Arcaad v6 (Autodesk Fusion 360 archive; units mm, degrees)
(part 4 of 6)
sketch "Sketch3" plane through (-5.5, 0, 0) normal (-1, 0, 0) x axis (0, -1, 0)
  line L1 (13, -14.5) -> (557.5, -14.5)
  circle C1 centre (557.5, -14.5) radius 7
  arc A1 centre (557.5, -14.5) radius 6.4 clockwise from (562.2211, -10.1789) to (562.7633, -10.8588)
  arc A2 centre (563.2662, -11.7231) radius 1 clockwise from (563.6284, -12.6553) to (562.7633, -10.8588)
  arc A3 centre (557.5, -14.5) radius 6.4 clockwise from (563.6284, -12.6553) to (563.8219, -13.5031)
  arc A4 centre (563.9, -14.5) radius 1 clockwise from (563.8219, -15.4969) to (563.8219, -13.5031)
  arc A5 centre (557.5, -14.5) radius 6.4 clockwise from (563.8219, -15.4969) to (563.6284, -16.3447)
  arc A6 centre (563.2662, -17.2769) radius 1 clockwise from (562.7633, -18.1412) to (563.6284, -16.3447)
  arc A7 centre (557.5, -14.5) radius 6.4 clockwise from (562.7633, -18.1412) to (562.2211, -18.8211)
  arc A8 centre (561.4903, -19.5037) radius 1 clockwise from (560.6622, -20.0642) to (562.2211, -18.8211)
  arc A9 centre (557.5, -14.5) radius 6.4 clockwise from (560.6622, -20.0642) to (559.8787, -20.4415)
  arc A10 centre (558.9241, -20.7395) radius 1 clockwise from (557.9348, -20.8852) to (559.8787, -20.4415)
  arc A11 centre (557.5, -14.5) radius 6.4 clockwise from (557.9348, -20.8852) to (557.0652, -20.8852)
  arc A12 centre (556.0759, -20.7395) radius 1 clockwise from (555.1213, -20.4415) to (557.0652, -20.8852)
  arc A13 centre (557.5, -14.5) radius 6.4 clockwise from (555.1213, -20.4415) to (554.3378, -20.0642)
  arc A14 centre (553.5097, -19.5037) radius 1 clockwise from (552.7789, -18.8211) to (554.3378, -20.0642)
  arc A15 centre (557.5, -14.5) radius 6.4 clockwise from (552.7789, -18.8211) to (552.2367, -18.1412)
  arc A16 centre (551.7338, -17.2769) radius 1 clockwise from (551.3716, -16.3447) to (552.2367, -18.1412)
  arc A17 centre (557.5, -14.5) radius 6.4 clockwise from (551.3716, -16.3447) to (551.1781, -15.4969)
  arc A18 centre (551.1, -14.5) radius 1 clockwise from (551.1781, -13.5031) to (551.1781, -15.4969)
  arc A19 centre (557.5, -14.5) radius 6.4 clockwise from (551.1781, -13.5031) to (551.3716, -12.6553)
  arc A20 centre (551.7338, -11.7231) radius 1 clockwise from (552.2367, -10.8588) to (551.3716, -12.6553)
  arc A21 centre (557.5, -14.5) radius 6.4 clockwise from (552.2367, -10.8588) to (552.7789, -10.1789)
  arc A22 centre (553.5097, -9.4963) radius 1 clockwise from (554.3378, -8.9358) to (552.7789, -10.1789)
  arc A23 centre (557.5, -14.5) radius 6.4 clockwise from (554.3378, -8.9358) to (555.1213, -8.5585)
  arc A24 centre (556.0759, -8.2605) radius 1 clockwise from (557.0652, -8.1148) to (555.1213, -8.5585)
  arc A25 centre (557.5, -14.5) radius 6.4 clockwise from (557.0652, -8.1148) to (557.9348, -8.1148)
  arc A26 centre (558.9241, -8.2605) radius 1 clockwise from (559.8787, -8.5585) to (557.9348, -8.1148)
  arc A27 centre (557.5, -14.5) radius 6.4 clockwise from (559.8787, -8.5585) to (560.6622, -8.9358)
  arc A28 centre (561.4903, -9.4963) radius 1 clockwise from (562.2211, -10.1789) to (560.6622, -8.9358)
  arc A29 centre (12.5, -14.5) radius 6.4 clockwise from (12.9348, -20.8852) to (12.9348, -8.1148)
  point P2 (557.5, -14.5)
  point P46 (557.5, -14.5)
  point P45 (13, -14.5)
  point P47 (13, -14.5)
  point P49 (12.9348, -8.1148)
  point P53 (12.9348, -8.1148)
  point P50 (12.9348, -20.8852)
  point P52 (12.9348, -20.8852)
  point P48 (12.5, -14.5)
  point P51 (12.5, -14.5)
  coincident P2 P46
  coincident P45 P47
  coincident P49 P53
  coincident P50 P52
  coincident P48 P51
sketch "Sketch4" plane through (0, 0, 0) normal (1, 0, 0) x axis (0, 0, -1)
sketch "Sketch5" plane through (-5.5, 0, 0) normal (-1, 0, 0) x axis (0, -1, 0)
sketch "Sketch6" plane through (-6, 0, 0) normal (-1, 0, 0) x axis (0, 0, 1)
  line L1 (-14.5, -13) -> (-14.5, -557.5)
  line L2 (-50, -285.25) -> (-14.5, -285.25)
  line L3 (20, -285.25) -> (-14.5, -285.25)
  line L4 (-20.8852, -285.25) -> (-20.8852, -12.9348)
  line L5 (-8.1148, -285.25) -> (-8.1148, -12.0652)
  line L6 (-20.8852, -285.25) -> (-20.8852, -557.5652)
  line L7 (-8.1148, -285.25) -> (-8.1148, -558.4348)
  circle C1 centre (-14.5, -12.5) radius 7
  arc A1 centre (-14.5, -12.5) radius 6.4 clockwise from (-10.1789, -17.2211) to (-10.8588, -17.7633)
  arc A2 centre (-11.7231, -18.2662) radius 1 clockwise from (-12.6553, -18.6284) to (-10.8588, -17.7633)
  arc A3 centre (-14.5, -12.5) radius 6.4 clockwise from (-12.6553, -18.6284) to (-13.5031, -18.8219)
  arc A4 centre (-14.5, -18.9) radius 1 clockwise from (-15.4969, -18.8219) to (-13.5031, -18.8219)
  arc A5 centre (-14.5, -12.5) radius 6.4 clockwise from (-15.4969, -18.8219) to (-16.3447, -18.6284)
  arc A6 centre (-17.2769, -18.2662) radius 1 clockwise from (-18.1412, -17.7633) to (-16.3447, -18.6284)
  arc A7 centre (-14.5, -12.5) radius 6.4 clockwise from (-18.1412, -17.7633) to (-18.8211, -17.2211)
  arc A8 centre (-19.5037, -16.4903) radius 1 clockwise from (-20.0642, -15.6622) to (-18.8211, -17.2211)
  arc A9 centre (-14.5, -12.5) radius 6.4 clockwise from (-20.0642, -15.6622) to (-20.4415, -14.8787)
  arc A10 centre (-20.7395, -13.9241) radius 1 clockwise from (-20.8852, -12.9348) to (-20.4415, -14.8787)
  arc A11 centre (-14.5, -12.5) radius 6.4 clockwise from (-20.8852, -12.9348) to (-20.8852, -12.0652)
  arc A12 centre (-20.7395, -11.0759) radius 1 clockwise from (-20.4415, -10.1213) to (-20.8852, -12.0652)
  arc A13 centre (-14.5, -12.5) radius 6.4 clockwise from (-20.4415, -10.1213) to (-20.0642, -9.3378)
  arc A14 centre (-19.5037, -8.5097) radius 1 clockwise from (-18.8211, -7.7789) to (-20.0642, -9.3378)
  arc A15 centre (-14.5, -12.5) radius 6.4 clockwise from (-18.8211, -7.7789) to (-18.1412, -7.2367)
  arc A16 centre (-17.2769, -6.7338) radius 1 clockwise from (-16.3447, -6.3716) to (-18.1412, -7.2367)
  arc A17 centre (-14.5, -12.5) radius 6.4 clockwise from (-16.3447, -6.3716) to (-15.4969, -6.1781)
  arc A18 centre (-14.5, -6.1) radius 1 clockwise from (-13.5031, -6.1781) to (-15.4969, -6.1781)
  arc A19 centre (-14.5, -12.5) radius 6.4 clockwise from (-13.5031, -6.1781) to (-12.6553, -6.3716)
  arc A20 centre (-11.7231, -6.7338) radius 1 clockwise from (-10.8588, -7.2367) to (-12.6553, -6.3716)
  arc A21 centre (-14.5, -12.5) radius 6.4 clockwise from (-10.8588, -7.2367) to (-10.1789, -7.7789)
  arc A22 centre (-9.4963, -8.5097) radius 1 clockwise from (-8.9358, -9.3378) to (-10.1789, -7.7789)
  arc A23 centre (-14.5, -12.5) radius 6.4 clockwise from (-8.9358, -9.3378) to (-8.5585, -10.1213)
  arc A24 centre (-8.2605, -11.0759) radius 1 clockwise from (-8.1148, -12.0652) to (-8.5585, -10.1213)
  arc A25 centre (-14.5, -12.5) radius 6.4 clockwise from (-8.1148, -12.0652) to (-8.1148, -12.9348)
  arc A26 centre (-8.2605, -13.9241) radius 1 clockwise from (-8.5585, -14.8787) to (-8.1148, -12.9348)
  arc A27 centre (-14.5, -12.5) radius 6.4 clockwise from (-8.5585, -14.8787) to (-8.9358, -15.6622)
  arc A28 centre (-9.4963, -16.4903) radius 1 clockwise from (-10.1789, -17.2211) to (-8.9358, -15.6622)
  arc A29 centre (-14.5, -12.5) radius 6.4 clockwise from (-20.8852, -12.9348) to (-8.1148, -12.9348)
  arc A30 centre (-14.5, -558) radius 6.4 clockwise from (-8.1148, -557.5652) to (-20.8852, -557.5652)
  point P40 (-8.1148, -12.9348)
  point P46 (-8.1148, -12.9348)
  point P17 (-20.8852, -12.9348)
  point P47 (-20.8852, -12.9348)
  point P50 (-14.5, -285.25)
  point P53 (-20.8852, -12.9348)
  point P54 (-20.8852, -285.25)
  point P38 (-8.1148, -12.0652)
  point P55 (-8.1148, -12.0652)
  point P56 (-8.1148, -285.25)
  point P58 (-8.1148, -557.5652)
  point P59 (-20.8852, -557.5652)
  point P60 (-20.8852, -557.5652)
  point P61 (-20.8852, -285.25)
  point P62 (-8.1148, -558.4348)
  point P63 (-8.1148, -285.25)
  coincident P40 P46
  coincident P17 P47
  midpoint L1 P50
  perpendicular L1 L2
  perpendicular L1 L3
  coincident P17 P53
  coincident L2 P54
  perpendicular L2 L4
  coincident P38 P55
  coincident L3 P56
  perpendicular L3 L5
  symmetric P46 L3 P58
  symmetric P47 L3 P59
  symmetric A29 L3 A30
  symmetric L3 P53 P60
  symmetric L3 P54 P61
  symmetric L3 P55 P62
  symmetric L3 P56 P63
work_plane "WorkPlane2" AlongDistance 0
work_plane "WorkPlane1" AlongDistance 0
sketch "Sketch7" plane through (-13, -13.8394, -20.222) normal (1, 0, 0) x axis (0, 0, -1)
  line L1 (0.6632, -271.4106) -> (0.6632, 0.9046)
  line L2 (-12.1072, -271.4106) -> (-12.1072, 1.7742)
  line L3 (0.6632, -271.4106) -> (0.6632, -543.7258)
  line L4 (-12.1072, -271.4106) -> (-12.1072, -544.5954)
  line L5 (-13.1072, -271.4106) -> (-13.1072, 1.7742)
  line L6 (1.6632, -271.4106) -> (1.6632, 0.9046)
  line L7 (-13.1072, -271.4106) -> (-13.1072, -544.5954)
  line L8 (1.6632, -271.4106) -> (1.6632, -543.7258)
  arc A1 centre (-5.722, 1.3394) radius 6.4 clockwise from (-12.1072, 0.9046) to (0.6632, 0.9046)
  arc A2 centre (-5.722, -544.1606) radius 6.4 clockwise from (0.6632, -543.7258) to (-12.1072, -543.7258)
  arc A3 centre (-5.722, 1.3394) radius 7.4 clockwise from (-13.1049, 0.8367) to (1.6609, 0.8367)
  arc A4 centre (-5.722, -544.1606) radius 7.4 clockwise from (1.6609, -543.6579) to (-13.1049, -543.6579)
  dimension "d24" = 1
  dimension "d25" = -1
  dimension "d26" = 1
  dimension "d27" = -1
  dimension "d28" = 1
  dimension "d29" = 1
extrude "Extrude5" new body sketch "Sketch7" along normal blind 7
copy_paste_bodies "CopyPasteBodies1"
move "Move1" TranslateX 0 TranslateY 0 TranslateZ -245
sketch "Sketch8" plane through (0, 0, 0) normal (-1, 0, 0) x axis (0, 0, 1)
  line L1 (13, -585) -> (-287, -585)
  line L2 (13, 15) -> (13, -585)
  line L3 (-287, 15) -> (13, 15)
  line L4 (-287, -585) -> (-287, 15)
  line L5 (-31.0605, -31.0605) -> (-243.9395, -31.0605)
  line L6 (-31.0605, -553.3145) -> (-31.0605, -31.0605)
  line L7 (-243.9395, -553.3145) -> (-31.0605, -553.3145)
  line L8 (-243.9395, -31.0605) -> (-243.9395, -553.3145)
  line L9 (318.9395, -553.3145) -> (318.9395, -31.0605)
  line L10 (106.0605, -553.3145) -> (318.9395, -553.3145)
  line L11 (318.9395, -31.0605) -> (106.0605, -31.0605)
  line L12 (106.0605, -31.0605) -> (106.0605, -553.3145)
  line L13 (106.0605, -513.3145) -> (318.9395, -513.3145)
  line L14 (-243.9395, -513.3145) -> (-31.0605, -513.3145)
  circle C1 centre (-259.5, -557.5) radius 2.5
  circle C2 centre (-14.5, -557.5) radius 2.5
  circle C3 centre (-259.5, -12.5) radius 2.5
  circle C4 centre (-14.5, -12.5) radius 2.5
  circle C5 centre (335.5, -557.5) radius 2.5
  circle C6 centre (90.5, -557.5) radius 2.5
  circle C7 centre (282.8591, -471.833) radius 20
  circle C8 centre (164.4009, -468.2067) radius 20
  circle C9 centre (225, -350) radius 20
  circle C10 centre (142.0186, -331.3336) radius 20
  circle C11 centre (226.3259, -235.6181) radius 20
  circle C12 centre (287.5847, -183.7959) radius 20
  circle C13 centre (162.57, -169.7572) radius 20
  circle C14 centre (129.8493, -225.5922) radius 20
  circle C15 centre (131.0664, -99.9179) radius 20
  circle C16 centre (214.8765, -425.1239) radius 15
  circle C17 centre (299.5333, -431.8087) radius 15
  circle C18 centre (260, -400) radius 15
  circle C19 centre (171.7339, -386.7903) radius 15
  circle C20 centre (195.3109, -315.7507) radius 15
  circle C21 centre (281.4332, -277.091) radius 15
  circle C22 centre (209.1847, -144.1327) radius 15
  circle C23 centre (211.4323, -94.5944) radius 15
  circle C24 centre (290.7241, -95.0468) radius 15
  circle C25 centre (210, -490) radius 10
  circle C26 centre (125.7856, -445.9118) radius 10
  circle C27 centre (130, -370) radius 10
  circle C28 centre (126.5404, -269.0631) radius 10
  circle C29 centre (176.569, -222.7107) radius 10
  circle C30 centre (233.5979, -275.0095) radius 10
  circle C31 centre (301.465, -233.4303) radius 10
  circle C32 centre (304.9225, -139.6703) radius 10
  circle C33 centre (260, -150) radius 10
  circle C34 centre (262.5929, -72.5429) radius 10
  circle C35 centre (122.2213, -136.25) radius 10
  circle C36 centre (219.3465, -184.5454) radius 10
  circle C37 centre (260, -440) radius 10
  circle C38 centre (304.2815, -314.2782) radius 10
  circle C39 centre (270, -320) radius 10
  circle C40 centre (177.2901, -424.5516) radius 10
  circle C41 centre (122.2213, -494.7374) radius 10
  circle C42 centre (298.2256, -504.4554) radius 10
  circle C43 centre (167.9513, -503.3757) radius 7
  circle C44 centre (244.5735, -496.3966) radius 7
  circle C45 centre (230, -460) radius 7
  circle C46 centre (183.3051, -345.8239) radius 7
  circle C47 centre (210, -390) radius 7
  circle C48 centre (150, -300) radius 7
  circle C49 centre (250, -120) radius 7
  circle C50 centre (168.2131, -77.1992) radius 7
  circle C51 centre (167.9513, -124.3724) radius 7
  circle C52 centre (140, -410) radius 7
  circle C53 centre (120, -180) radius 7
  circle C54 centre (193.9116, -281.9568) radius 7
  circle C55 centre (272.9439, -242.5691) radius 7
  circle C56 centre (183.3051, -345.8239) radius 7
  circle C57 centre (183.3051, -345.8239) radius 7
  circle C58 centre (212.9765, -58.095) radius 7
  circle C59 centre (122.1145, -62.8164) radius 7
  circle C60 centre (290, -60) radius 7
  circle C61 centre (289.7934, -358.0992) radius 20
  circle C62 centre (299.2119, -395.8727) radius 7
  circle C63 centre (168.3396, -262.778) radius 10
  circle C64 centre (259.0485, -202.6198) radius 7
  circle C65 centre (-105.4265, -496.3966) radius 7
  circle C66 centre (-50.7881, -395.8727) radius 7
  circle C67 centre (-182.0487, -503.3757) radius 7
  circle C68 centre (-172.7099, -424.5516) radius 10
  circle C69 centre (-140, -390) radius 7
  circle C70 centre (-178.2661, -386.7903) radius 15
  circle C71 centre (-166.6949, -345.8239) radius 7
  circle C72 centre (-166.6949, -345.8239) radius 7
  circle C73 centre (-60.2066, -358.0992) radius 20
  circle C74 centre (-185.5991, -468.2067) radius 20
  circle C75 centre (-227.8855, -62.8164) radius 7
  circle C76 centre (-135.1235, -425.1239) radius 15
  circle C77 centre (-80, -320) radius 10
  circle C78 centre (-51.7744, -504.4554) radius 10
  circle C79 centre (-45.7185, -314.2782) radius 10
  circle C80 centre (-48.535, -233.4303) radius 10
  circle C81 centre (-120, -460) radius 7
  circle C82 centre (-116.4021, -275.0095) radius 10
  circle C83 centre (-166.6949, -345.8239) radius 7
  circle C84 centre (-50.4667, -431.8087) radius 15
  circle C85 centre (-227.7787, -494.7374) radius 10
  circle C86 centre (-210, -410) radius 7
  circle C87 centre (-220, -370) radius 10
  circle C88 centre (-90, -440) radius 10
  circle C89 centre (-90, -400) radius 15
  circle C90 centre (-67.1409, -471.833) radius 20
  circle C91 centre (-224.2144, -445.9118) radius 10
  circle C92 centre (-140, -490) radius 10
  circle C93 centre (-125, -350) radius 20
  circle C94 centre (-68.5668, -277.091) radius 15
  circle C95 centre (-62.4153, -183.7959) radius 20
  circle C96 centre (-230, -180) radius 7
  circle C97 centre (-181.6604, -262.778) radius 10
  circle C98 centre (-218.9336, -99.9179) radius 20
  circle C99 centre (-181.7869, -77.1992) radius 7
  circle C100 centre (-138.5677, -94.5944) radius 15
  circle C101 centre (-90.9515, -202.6198) radius 7
  circle C102 centre (-154.6891, -315.7507) radius 15
  circle C103 centre (-130.6535, -184.5454) radius 10
  circle C104 centre (-60, -60) radius 7
  circle C105 centre (-200, -300) radius 7
  circle C106 centre (-220.1507, -225.5922) radius 20
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  dimension "d87" = 40
  dimension "d92" diameter C7 = 40
  dimension "d93" diameter C8 = 40
  dimension "d94" diameter C9 = 40
  dimension "d95" diameter C10 = 40
  dimension "d97" diameter C11 = 40
  dimension "d98" diameter C12 = 40
  dimension "d99" diameter C13 = 40
  dimension "d100" diameter C14 = 40
  dimension "d101" diameter C15 = 40
  dimension "d102" diameter C16 = 30
  dimension "d103" diameter C17 = 30
  dimension "d104" diameter C18 = 30
  dimension "d105" diameter C19 = 30
  dimension "d106" diameter C20 = 30
  dimension "d107" diameter C21 = 30
  dimension "d108" diameter C22 = 30
  dimension "d109" diameter C23 = 30
  dimension "d110" diameter C24 = 30
  dimension "d111" diameter C25 = 20
  dimension "d112" diameter C26 = 20
  dimension "d113" diameter C27 = 20
  dimension "d114" diameter C28 = 20
  dimension "d115" diameter C29 = 20
  dimension "d116" diameter C30 = 20
  dimension "d117" diameter C31 = 20
  dimension "d118" diameter C32 = 20
  dimension "d119" diameter C33 = 20
  dimension "d120" diameter C34 = 20
  dimension "d121" diameter C35 = 20
  dimension "d123" diameter C36 = 20
  dimension "d124" diameter C37 = 20
  dimension "d125" diameter C38 = 20
  dimension "d126" diameter C39 = 20
  dimension "d127" diameter C40 = 20
  dimension "d128" diameter C41 = 20
  dimension "d129" diameter C42 = 20
  dimension "d130" diameter C43 = 14
  dimension "d131" diameter C44 = 14
  dimension "d132" diameter C45 = 14
  dimension "d133" diameter C46 = 14
  dimension "d134" diameter C47 = 14
  dimension "d135" diameter C48 = 14
  dimension "d136" diameter C49 = 14
  dimension "d137" diameter C50 = 14
  dimension "d138" diameter C51 = 14
  dimension "d139" diameter C52 = 14
  dimension "d140" diameter C53 = 14
  dimension "d141" diameter C54 = 14
  dimension "d142" diameter C55 = 14
  dimension "d143" diameter C56 = 14
  dimension "d144" diameter C57 = 14
  dimension "d145" diameter C58 = 14
  dimension "d146" diameter C59 = 14
  dimension "d147" diameter C60 = 14
  dimension "d148" diameter C61 = 40
  dimension "d149" diameter C62 = 14
  dimension "d150" diameter C63 = 20
  dimension "d151" diameter C64 = 14
  dimension "d152" diameter C90 = 40
  dimension "d153" diameter C74 = 40
  dimension "d154" diameter C93 = 40
  dimension "d155" diameter = 40
  dimension "d156" diameter = 40
  dimension "d157" diameter C95 = 40
  dimension "d158" diameter = 40
  dimension "d159" diameter C106 = 40
  dimension "d160" diameter C98 = 40
  dimension "d161" diameter C76 = 30
  dimension "d162" diameter C84 = 30
  dimension "d163" diameter C89 = 30
  dimension "d164" diameter C70 = 30
  dimension "d165" diameter C102 = 30
  dimension "d166" diameter C94 = 30
  dimension "d167" diameter = 30
  dimension "d168" diameter C100 = 30
  dimension "d169" diameter = 30
  dimension "d170" diameter C92 = 20
  dimension "d171" diameter C91 = 20
  dimension "d172" diameter C87 = 20
  dimension "d173" diameter = 20
  dimension "d174" diameter = 20
  dimension "d175" diameter C82 = 20
  dimension "d176" diameter C80 = 20
  dimension "d177" diameter = 20
  dimension "d178" diameter = 20
  dimension "d179" diameter = 20
  dimension "d180" diameter = 20
  dimension "d181" diameter C103 = 20
  dimension "d182" diameter C88 = 20
  dimension "d183" diameter C79 = 20
  dimension "d184" diameter C77 = 20
  dimension "d185" diameter C68 = 20
  dimension "d186" diameter C85 = 20
  dimension "d187" diameter C78 = 20
  dimension "d188" diameter C67 = 14
  dimension "d189" diameter C65 = 14
  dimension "d190" diameter C81 = 14
  dimension "d191" diameter C72 = 14
  dimension "d192" diameter C69 = 14
  dimension "d193" diameter C105 = 14
  dimension "d194" diameter = 14
  dimension "d195" diameter C99 = 14
  dimension "d196" diameter = 14
  dimension "d197" diameter C86 = 14
  dimension "d198" diameter C96 = 14
  dimension "d199" diameter = 14
  dimension "d200" diameter = 14
  dimension "d201" diameter C71 = 14
  dimension "d202" diameter C83 = 14
  dimension "d203" diameter = 14
  dimension "d204" diameter C75 = 14
  dimension "d205" diameter C104 = 14
  dimension "d206" diameter C73 = 40
  dimension "d207" diameter C66 = 14
  dimension "d208" diameter C97 = 20
  dimension "d209" diameter C101 = 14
extrude "Extrude6" cut sketch "Sketch8" to an object
sketch "Sketch1" plane through (0, 0, 0) normal (1, 0, 0) x axis (0, 1, 0)
  line L1
  line L2 (10.6725, 42.0131) -> (-11.493, 42.0131)
  line L3
  line L4 (-10.938, 45.9426) -> (-10.938, 45.9976)
  line L5 (10.6725, 49.1774) -> (10.6725, 46.7526)
  line L6 (10.6725, 44.9776) -> (10.6725, 42.0131)
  line L7 (-11.493, 42.0131) -> (-11.493, 44.9776)
  line L8 (-10.0325, 45.9976) -> (-10.0325, 45.9426)
  line L9 (-11.493, 46.7526) -> (-11.493, 49.1774)
  line L10 (-8.2175, 45.9976) -> (-8.2175, 45.9928)
  line L11 (-8.2175, 45.9928) -> (-8.723, 45.9928)
  line L12 (-8.723, 45.9928) -> (-8.723, 45.9976)
  line L13 (-10.2325, 45.9976) -> (-10.2325, 45.9928)
  line L14 (-10.2325, 45.9928) -> (-10.738, 45.9928)
  line L15 (-10.738, 45.9928) -> (-10.738, 45.9976)
  line L16 (-6.708, 45.9928) -> (-6.708, 45.9976)
  line L17 (-6.2025, 45.9976) -> (-6.2025, 45.9928)
  line L18 (-6.2025, 45.9928) -> (-6.708, 45.9928)
  line L19 (-4.693, 45.9928) -> (-4.693, 45.9976)
  line L20 (-4.1875, 45.9976) -> (-4.1875, 45.9928)
  line L21 (-4.1875, 45.9928) -> (-4.693, 45.9928)
  line L22 (-2.678, 45.9928) -> (-2.678, 45.9976)
  line L23 (-2.1725, 45.9976) -> (-2.1725, 45.9928)
  line L24 (-2.1725, 45.9928) -> (-2.678, 45.9928)
  line L25 (-0.663, 45.9928) -> (-0.663, 45.9976)
  line L26 (-0.1575, 45.9976) -> (-0.1575, 45.9928)
  line L27 (-0.1575, 45.9928) -> (-0.663, 45.9928)
  line L28 (1.352, 45.9928) -> (1.352, 45.9976)
  line L29 (1.8575, 45.9976) -> (1.8575, 45.9928)
  line L30 (1.8575, 45.9928) -> (1.352, 45.9928)
  line L31 (3.367, 45.9928) -> (3.367, 45.9976)
  line L32 (3.8725, 45.9976) -> (3.8725, 45.9928)
  line L33 (3.8725, 45.9928) -> (3.367, 45.9928)
  line L34 (5.382, 45.9928) -> (5.382, 45.9976)
  line L35 (5.8875, 45.9976) -> (5.8875, 45.9928)
  line L36 (5.8875, 45.9928) -> (5.382, 45.9928)
  line L37 (7.397, 45.9928) -> (7.397, 45.9976)
  line L38 (7.9025, 45.9976) -> (7.9025, 45.9928)
  line L39 (7.9025, 45.9928) -> (7.397, 45.9928)
  line L40 (9.412, 45.9928) -> (9.412, 45.9976)
  line L41 (9.9175, 45.9976) -> (9.9175, 45.9928)
  line L42 (9.9175, 45.9928) -> (9.412, 45.9928)
  line L43 (11.427, 45.9928) -> (11.427, 45.9976)
  arc A1 centre (-7.4625, 45.9976) radius 0.755 clockwise from (-8.2175, 45.9976) to (-7.4625, 46.7526)
  arc A2 centre (-9.478, 45.9976) radius 0.755 clockwise from (-9.478, 46.7526) to (-8.723, 45.9976)
  arc A3 centre (-9.4775, 45.9976) radius 0.755 clockwise from (-10.2325, 45.9976) to (-9.4777, 46.7526)
  arc A4 centre (-11.493, 45.9976) radius 0.755 clockwise from (-11.493, 46.7526) to (-10.738, 45.9976)
  arc A5 centre (-7.463, 45.9976) radius 0.755 clockwise from (-7.463, 46.7526) to (-6.708, 45.9976)
  arc A6 centre (-5.4475, 45.9976) radius 0.755 clockwise from (-6.2025, 45.9976) to (-5.4475, 46.7526)
  arc A7 centre (-5.448, 45.9976) radius 0.755 clockwise from (-5.448, 46.7526) to (-4.693, 45.9976)
  arc A8 centre (-3.4325, 45.9976) radius 0.755 clockwise from (-4.1875, 45.9976) to (-3.4325, 46.7526)
  arc A9 centre (-3.433, 45.9976) radius 0.755 clockwise from (-3.433, 46.7526) to (-2.678, 45.9976)
  arc A10 centre (-1.4175, 45.9976) radius 0.755 clockwise from (-2.1725, 45.9976) to (-1.4175, 46.7526)
  arc A11 centre (-1.418, 45.9976) radius 0.755 clockwise from (-1.418, 46.7526) to (-0.663, 45.9976)
  arc A12 centre (0.5975, 45.9976) radius 0.755 clockwise from (-0.1575, 45.9976) to (0.5975, 46.7526)
  arc A13 centre (0.597, 45.9976) radius 0.755 clockwise from (0.597, 46.7526) to (1.352, 45.9976)
  arc A14 centre (2.6125, 45.9976) radius 0.755 clockwise from (1.8575, 45.9976) to (2.6125, 46.7526)
  arc A15 centre (2.612, 45.9976) radius 0.755 clockwise from (2.612, 46.7526) to (3.367, 45.9976)
  arc A16 centre (4.6275, 45.9976) radius 0.755 clockwise from (3.8725, 45.9976) to (4.6275, 46.7526)
  arc A17 centre (4.627, 45.9976) radius 0.755 clockwise from (4.627, 46.7526) to (5.382, 45.9976)
  arc A18 centre (6.6425, 45.9976) radius 0.755 clockwise from (5.8875, 45.9976) to (6.6425, 46.7526)
  arc A19 centre (6.642, 45.9976) radius 0.755 clockwise from (6.642, 46.7526) to (7.397, 45.9976)
  arc A20 centre (8.6575, 45.9976) radius 0.755 clockwise from (7.9025, 45.9976) to (8.6575, 46.7526)
  arc A21 centre (8.657, 45.9976) radius 0.755 clockwise from (8.657, 46.7526) to (9.412, 45.9976)
  arc A22 centre (10.6725, 45.9976) radius 0.755 clockwise from (9.9175, 45.9976) to (10.6725, 46.7526)
  point P92 (-9.4777, 46.7526)
  point P93 (-7.4625, 46.7526)
  point P94 (-5.4475, 46.7526)
  point P95 (-3.4325, 46.7526)
  point P96 (-1.4175, 46.7526)
  point P97 (0.5975, 46.7526)
  point P98 (2.6125, 46.7526)
  point P99 (4.6275, 46.7526)
  point P100 (6.6425, 46.7526)
  point P101 (8.6575, 46.7526)
  point P26 (-6.708, 45.9976)
  tangent L15 A4
  tangent A3 L13
  tangent L12 A2
  tangent A1 L10
  coincident A2 P92
  coincident A5 P93
  coincident A7 P94
  coincident A9 P95
  coincident A11 P96
  coincident A13 P97
  coincident A15 P98
  coincident A17 P99
  coincident A19 P100
  coincident A21 P101
  dimension "d9_1" distance L1 P26 = 1.02
  dimension "d6" R-Pattern1-uDistance = 20.15 (= "( 2.015 * 10 ) * 1 mm")
  dimension "d7" R-Pattern1-vDistance = 0
extrude "Extrude1" new body sketch "Sketch1" profile of L1 L2 L3 L5 L6 L7 L9 A1 L10 L11 L12 A2 A3 L14 L13 L15 A4 A5 A6 L16 L17 L18 A7 A8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 against normal blind 7 named "d10_1"
sketch "Sketch2" plane through (-7, 0, 0) normal (-1, 0, 0) x axis (0, -1, 0)
  line L1 (-9.412, 45.9976) -> (-9.412, 45.9928)
  line L2 (-7.9025, 45.9928) -> (-7.9025, 45.9976)
  line L3 (-7.397, 45.9928) -> (-7.9025, 45.9928)
  line L4 (-7.397, 45.9976) -> (-7.397, 45.9928)
  line L5 (-5.8875, 45.9928) -> (-5.8875, 45.9976)
  line L6 (-5.382, 45.9928) -> (-5.8875, 45.9928)
  line L7 (-5.382, 45.9976) -> (-5.382, 45.9928)
  line L8 (-3.8725, 45.9928) -> (-3.8725, 45.9976)
  line L9 (-3.367, 45.9928) -> (-3.8725, 45.9928)
  line L10 (-3.367, 45.9976) -> (-3.367, 45.9928)
  line L11 (-1.8575, 45.9928) -> (-1.8575, 45.9976)
  line L12 (-1.352, 45.9928) -> (-1.8575, 45.9928)
  line L13 (-1.352, 45.9976) -> (-1.352, 45.9928)
  line L14 (0.1575, 45.9928) -> (0.1575, 45.9976)
  line L15 (0.663, 45.9928) -> (0.1575, 45.9928)
  line L16 (0.663, 45.9976) -> (0.663, 45.9928)
  line L17 (2.1725, 45.9928) -> (2.1725, 45.9976)
  line L18 (2.678, 45.9928) -> (2.1725, 45.9928)
  line L19 (2.678, 45.9976) -> (2.678, 45.9928)
  line L20 (4.1875, 45.9928) -> (4.1875, 45.9976)
  line L21 (4.693, 45.9928) -> (4.1875, 45.9928)
  line L22 (4.693, 45.9976) -> (4.693, 45.9928)
  line L23 (6.2025, 45.9928) -> (6.2025, 45.9976)
  line L24 (6.708, 45.9928) -> (6.2025, 45.9928)
  line L25 (6.708, 45.9976) -> (6.708, 45.9928)
  line L26 (8.2175, 45.9928) -> (8.2175, 45.9976)
  line L27 (8.723, 45.9928) -> (8.2175, 45.9928)
  line L28 (8.723, 45.9976) -> (8.723, 45.9928)
  line L29 (10.2325, 45.9928) -> (10.2325, 45.9976)
  line L30 (10.738, 45.9928) -> (10.2325, 45.9928)
  line L31 (10.738, 45.9976) -> (10.738, 45.9928)
  line L32 (11.493, 49.1774) -> (11.493, 46.7526)
  line L33
  line L34 (-10.6725, 46.7526) -> (-10.6725, 49.1774)
  line L35 (-9.9175, 45.9928) -> (-9.9175, 45.9976)
  line L36 (-9.412, 45.9928) -> (-9.9175, 45.9928)
  line L37 (-10.6725, 44.9776) -> (-10.6725, 46.7526)
  line L38 (11.493, 44.9776) -> (11.493, 46.7526)
  line L39 (11.493, 44.9776) -> (11.493, 42.0131)
  line L40
  line L41 (-10.6725, 42.0131) -> (-10.6725, 44.9776)
  line L42 (11.493, 42.0131) -> (-10.6725, 42.0131)
  arc A1 centre (-8.657, 45.9976) radius 0.755 clockwise from (-9.412, 45.9976) to (-8.657, 46.7526)
  arc A2 centre (-8.6575, 45.9976) radius 0.755 clockwise from (-8.657, 46.7526) to (-7.9025, 45.9976)
  arc A3 centre (-6.642, 45.9976) radius 0.755 clockwise from (-7.397, 45.9976) to (-6.642, 46.7526)
  arc A4 centre (-6.6425, 45.9976) radius 0.755 clockwise from (-6.642, 46.7526) to (-5.8875, 45.9976)
  arc A5 centre (-4.627, 45.9976) radius 0.755 clockwise from (-5.382, 45.9976) to (-4.627, 46.7526)
  arc A6 centre (-4.6275, 45.9976) radius 0.755 clockwise from (-4.627, 46.7526) to (-3.8725, 45.9976)
  arc A7 centre (-2.612, 45.9976) radius 0.755 clockwise from (-3.367, 45.9976) to (-2.612, 46.7526)
  arc A8 centre (-2.6125, 45.9976) radius 0.755 clockwise from (-2.612, 46.7526) to (-1.8575, 45.9976)
  arc A9 centre (-0.597, 45.9976) radius 0.755 clockwise from (-1.352, 45.9976) to (-0.597, 46.7526)
  arc A10 centre (-0.5975, 45.9976) radius 0.755 clockwise from (-0.597, 46.7526) to (0.1575, 45.9976)
  arc A11 centre (1.418, 45.9976) radius 0.755 clockwise from (0.663, 45.9976) to (1.418, 46.7526)
  arc A12 centre (1.4175, 45.9976) radius 0.755 clockwise from (1.418, 46.7526) to (2.1725, 45.9976)
  arc A13 centre (3.433, 45.9976) radius 0.755 clockwise from (2.678, 45.9976) to (3.433, 46.7526)
  arc A14 centre (3.4325, 45.9976) radius 0.755 clockwise from (3.433, 46.7526) to (4.1875, 45.9976)
  arc A15 centre (5.448, 45.9976) radius 0.755 clockwise from (4.693, 45.9976) to (5.448, 46.7526)
  arc A16 centre (5.4475, 45.9976) radius 0.755 clockwise from (5.448, 46.7526) to (6.2025, 45.9976)
  arc A17 centre (7.463, 45.9976) radius 0.755 clockwise from (6.708, 45.9976) to (7.463, 46.7526)
  arc A18 centre (7.4625, 45.9976) radius 0.755 clockwise from (7.463, 46.7526) to (8.2175, 45.9976)
  arc A19 centre (9.478, 45.9976) radius 0.755 clockwise from (8.723, 45.9976) to (9.4777, 46.7526)
  arc A20 centre (9.4775, 45.9976) radius 0.755 clockwise from (9.4777, 46.7526) to (10.2325, 45.9976)
  arc A21 centre (11.493, 45.9976) radius 0.755 clockwise from (10.738, 45.9976) to (11.493, 46.7526)
  arc A22 centre (-10.6725, 45.9976) radius 0.755 clockwise from (-10.6725, 46.7526) to (-9.9175, 45.9976)
  point P96 (-10.6725, 46.7526)
  point P102 (-10.6725, 46.7526)
  point P101 (-10.6725, 44.9776)
  point P103 (-10.6725, 44.9776)
  point P92 (11.493, 46.7526)
  point P105 (11.493, 46.7526)
  point P104 (11.493, 44.9776)
  point P106 (11.493, 44.9776)
  coincident P96 P102
  coincident P101 P103
  coincident P92 P105
  coincident P104 P106
extrude "Extrude2" add sketch "Sketch2" along normal blind 3 named "d12_1"
sketch "Sketch3" plane through (0, -11.493, 0) normal (0, -1, 0) x axis (1, 0, 0)
  line L1 (0, 44.9776) -> (0, 42.0131)
  line L2 (-7, 44.9776) -> (0, 44.9776)
  line L3 (-7, 46.7526) -> (-7, 44.9776)
  line L4 (0, 46.7526) -> (-7, 46.7526)
  line L5 (0, 49.1774) -> (0, 46.7526)
  line L6 (-10, 49.1774) -> (0, 49.1774)
  line L7 (-10, 42.0131) -> (-10, 49.1774)
  line L8 (0, 42.0131) -> (-10, 42.0131)
  line L9 (-16.5, 42.0131) -> (-10, 42.0131)
  line L10 (-16.5, 48.1131) -> (-10, 48.1131)
  line L11 (-16.5, 42.8589) -> (0, 42.8589)
  line L12 (-16.5, 42.0131) -> (-16.5, 48.1131)
  line L13 (-16.5, 43.8589) -> (0, 43.8589)
  line L14 (-3.509, 42.8589) -> (-3.509, 43.8589)
  line L15 (-18.456, 42.0131) -> (-18.456, 48.1131)
  line L16 (-18.456, 42.0131) -> (-16.5, 42.0131)
  line L17 (-16.5, 48.1131) -> (-18.456, 48.1131)
  line L18 (-16.5, 41.1131) -> (-16.5, 42.0131)
  line L19 (-18.456, 48.4131) -> (-18.456, 48.1131)
  line L20 (-18.456, 41.7131) -> (-18.456, 42.0131)
  line L21 (-16.5, 41.1131) -> (-18.456, 41.7131)
  line L22 (-18.456, 42.8589) -> (-16.5, 42.8589)
  line L23 (-18.456, 46.3806) -> (-10, 46.3806)
  line L24 (-10, 45.2617) -> (-16.5, 45.2459)
  line L25 (-16.5, 49.0131) -> (-16.5, 48.1131)
  line L26 (-16.5, 49.0131) -> (-18.456, 48.4131)
  arc A1 centre (-5.3313, 43.3589) radius 0.5 clockwise from (-5.3313, 43.8589) to (-5.3313, 42.8589)
  arc A2 centre (-10, 45.8212) radius 0.5594 clockwise from (-10, 46.3806) to (-10, 45.2617)
  point P9 (-10, 42.0131)
  point P10 (-10, 42.0131)
  point P14 (0, 42.8589)
  point P15 (-16.5, 42.8589)
  point P18 (-3.509, 43.8589)
  point P19 (-3.509, 42.8589)
  point P26 (-18.456, 42.8589)
  point P27 (-10, 46.3806)
  point P28 (-18.456, 46.3806)
  point P29 (-16.5, 45.2459)
  point P30 (-10, 45.2617)
  point P31 (-5.3313, 43.8589)
  point P32 (-5.3313, 42.8589)
  point P11 (-16.5, 42.0131)
  point P22 (-16.5, 41.1131)
  point P21 (-18.456, 42.0131)
  point P24 (-18.456, 41.7131)
  point P20 (-18.456, 48.1131)
  point P23 (-18.456, 48.4131)
  point P13 (-16.5, 48.1131)
  point P34 (-16.5, 49.0131)
  coincident P9 P10
  perpendicular L7 L9
  coincident L1 P14
  perpendicular L7 L11
  perpendicular L9 L12
  coincident L12 P15
  coincident L13 P18
  coincident L11 P19
  perpendicular L11 L14
  parallel L12 L15
  perpendicular L15 L16
  perpendicular L12 L17
  perpendicular L9 L18
  perpendicular L17 L19
  perpendicular L16 L20
  tangent L11 A1
  coincident L15 P26
  perpendicular L15 L22
  coincident L7 P27
  coincident L15 P28
  perpendicular L15 L23
  coincident L12 P29
  coincident L7 P30
  coincident L13 P31
  coincident L11 P32
  perpendicular L10 L25
  dimension "d14_1" = 6.1
  dimension "d15" distance P10 P11 = 6.5
  dimension "d16_1" = 1
  dimension "d18_1" distance P11 P22 = 0.9
  dimension "d19_1" distance P21 P24 = 0.3
  dimension "d20_1" distance P20 P23 = 0.3
  dimension "d27_1" distance P13 P34 = 0.9
extrude "Extrude5" add sketch "Sketch3" profile of L7 L9 L10 L11 L12 L13 L15 L16 L17 L18 L19 L20 L21 L22 L23 L24 L25 L26 to an object
extrude "Extrude3" cut sketch "Sketch3" profile of L7 L11 L13 A1 A2 against normal blind 29 named "d22_1"
sketch "Sketch4" plane through (0, -11.493, 0) normal (0, -1, 0) x axis (1, 0, 0)
  line L1 (-5.3313, 43.8589) -> (-16.5, 43.8589)
  line L2 (-18.456, 42.8589) -> (-5.3313, 42.8589)
  line L3 (-18.456, 41.7131) -> (-18.456, 42.8589)
  line L4 (-16.5, 41.1131) -> (-18.456, 41.7131)
  line L5 (-16.5, 42.0131) -> (-16.5, 41.1131)
  line L6 (0, 42.0131) -> (-16.5, 42.0131)
  line L7 (0, 44.9776) -> (0, 42.0131)
  line L8 (-7, 44.9776) -> (0, 44.9776)
  line L9 (-7, 46.7526) -> (-7, 44.9776)
  line L10 (0, 46.7526) -> (-7, 46.7526)
  line L11 (0, 49.1774) -> (0, 46.7526)
  line L12 (-10, 49.1774) -> (0, 49.1774)
  line L13 (-10, 48.1131) -> (-10, 49.1774)
  line L14 (-16.5, 48.1131) -> (-10, 48.1131)
  line L15 (-16.5, 49.0131) -> (-16.5, 48.1131)
  line L16 (-18.456, 48.4131) -> (-16.5, 49.0131)
  line L17 (-18.456, 46.3806) -> (-18.456, 48.4131)
  line L18 (-10, 46.3806) -> (-18.456, 46.3806)
  line L19 (-16.5, 45.2459) -> (-10, 45.2617)
  line L20 (-16.5, 43.8589) -> (-16.5, 45.2459)
  line L21 (-10, 40.2406) -> (-10, 48.1131)
  line L22 (0.0324, 40.5397) -> (-10, 40.5397)
  line L23 (0, 42.0131) -> (0.0324, 40.5397)
  arc A1 centre (-5.3313, 43.3589) radius 0.5 clockwise from (-5.3313, 43.8589) to (-5.3313, 42.8589)
  arc A2 centre (-10, 45.8212) radius 0.5594 clockwise from (-10, 46.3806) to (-10, 45.2617)
  point P17 (-10, 48.1131)
  point P26 (-10, 48.1131)
  point P28 (-10, 40.5397)
  point P10 (0, 42.0131)
  point P30 (0, 42.0131)
  coincident P17 P26
  perpendicular L6 L21
  coincident L21 P28
  perpendicular L21 L22
  coincident P10 P30
extrude "Extrude6" add sketch "Sketch4" profile of L6 L21 L22 L23 against normal blind 22.165 named "d30_1"
extrude "Extrude7" add of existing geometry blind -2 named "d32_1"
extrude "Extrude8" add of existing geometry blind 0.0005 (= "4.928E-04 mm") named "d34_1"
extrude "Extrude9" cut of existing geometry blind -0.032 named "d36_1"
extrude "Extrude10" cut of existing geometry blind -0.0004 (= "-4.004E-04 mm")
sketch "Sketch5" plane through (0, -11.493, 0) normal (0, -1, 0) x axis (1, 0, 0)
  line L1 (0, 44.9776) -> (0, 40.5397)
  line L2 (-7, 44.9776) -> (0, 44.9776)
  line L3 (-7, 46.7526) -> (-7, 44.9776)
  line L4 (0, 46.7526) -> (-7, 46.7526)
  line L5 (0, 49.1774) -> (0, 46.7526)
  line L6 (-10, 49.1774) -> (0, 49.1774)
  line L7 (-10, 48.1131) -> (-10, 49.1774)
  line L8 (-16.5, 48.1131) -> (-10, 48.1131)
  line L9 (-16.5, 49.0131) -> (-16.5, 48.1131)
  line L10 (-18.456, 48.4131) -> (-16.5, 49.0131)
  line L11 (-18.456, 46.3806) -> (-18.456, 48.4131)
  line L12 (-10, 46.3806) -> (-18.456, 46.3806)
  line L13 (-16.5, 45.2459) -> (-10, 45.2617)
  line L14 (-16.5, 43.8589) -> (-16.5, 45.2459)
  line L15 (-5.3313, 43.8589) -> (-16.5, 43.8589)
  line L16 (-18.456, 42.8589) -> (-5.3313, 42.8589)
  line L17 (-18.456, 41.7131) -> (-18.456, 42.8589)
  line L18 (-16.5, 41.1131) -> (-18.456, 41.7131)
  line L19 (-16.5, 42.0131) -> (-16.5, 41.1131)
  line L20 (-10, 42.0131) -> (-16.5, 42.0131)
  line L21 (-10, 40.5397) -> (-10, 42.0131)
  line L22 (0, 40.5397) -> (-10, 40.5397)
  line L23 (0.5597, 42.0131) -> (-10, 42.0131)
  line L24 (-7, 39.917) -> (-7, 44.9776)
  arc A1 centre (-10, 45.8212) radius 0.5594 clockwise from (-10, 46.3806) to (-10, 45.2617)
  arc A2 centre (-5.3313, 43.3589) radius 0.5 clockwise from (-5.3313, 43.8589) to (-5.3313, 42.8589)
  point P26 (-10, 42.0131)
  point P28 (-10, 42.0131)
  point P4 (-7, 44.9776)
  point P30 (-7, 44.9776)
  coincident P26 P28
  perpendicular L1 L23
  coincident P4 P30
  perpendicular L22 L24
extrude "Extrude11" cut sketch "Sketch5" profile of L1 L22 L23 L24 against normal blind 28
offset_faces "OffsetFaces1" distance 0.6
extrude "Extrude12" add of existing geometry blind 0.6
fillet "Fillet2" radius 1
extrude "Extrude13" add of existing geometry blind 5
extrude "Extrude14" add of existing geometry blind 3
sketch "Sketch6" plane through (-7, 0, 0) normal (1, 0, 0) x axis (0, 1, 0)
  line L1 (10.6725, 42.0131) -> (10.6725, 32.5397)
  line L2
  line L3 (-11.493, 32.5397) -> (-11.493, 42.0131)
  line L4 (10.6725, 32.5397) -> (-11.493, 32.5397)
  line L5 (-0.4102, 35.5397) -> (-0.4102, 32.5397)
  circle C1 centre (-0.4102, 35.5397) radius 3
  point P6 (-0.4102, 32.5397)
  point P7 (-0.4102, 35.5397)
  point P8 (-0.4102, 35.5397)
  midpoint L4 P6
  perpendicular L4 L5
  coincident P7 P8
  coincident P6 C1
  dimension "d50" distance P6 P7 = 3
extrude "Extrude15" add sketch "Sketch6" profile of C1 to an object
position "Position5"
sketch "Sketch9" plane through (6, 0, 0) normal (1, 0, 0) x axis (0, 0, -1)
  line L1 (-2.3267, -33.65) -> (31.3267, -33.65)
  line L2 (-6.5036, -29.6802) -> (-2.6802, -33.5036)
  line L3 (-6.65, 4.3267) -> (-6.65, -29.3267)
  line L4 (-2.6802, 8.5036) -> (-6.5036, 4.6802)
  line L5 (31.3267, 8.65) -> (-2.3267, 8.65)
  line L6 (35.5036, 4.6802) -> (31.6802, 8.5036)
  line L7 (35.65, -29.3267) -> (35.65, 4.3267)
  line L8 (31.6802, -33.5036) -> (35.5036, -29.6802)
  line L9 (287, -585) -> (-13, -585)
  line L10 (287, 15) -> (287, -585)
  line L11 (-13, 15) -> (287, 15)
  line L12 (-13, -585) -> (-13, 15)
  line L13 (24.0039, -461.493) -> (20.4822, -461.493)
  line L14 (24.0039, -471.8239) -> (24.0039, -461.493)
  line L15 (20.4822, -471.8239) -> (24.0039, -471.8239)
  line L16 (20.4822, -461.493) -> (20.4822, -471.8239)
  circle C1 centre (259.5, -557.5) radius 2.5
  circle C2 centre (14.5, -557.5) radius 2.5
  circle C3 centre (259.5, -12.5) radius 11
  arc A1 centre (-2.3267, -33.15) radius 0.5 clockwise from (-2.3267, -33.65) to (-2.6802, -33.5036)
  arc A2 centre (-6.15, -29.3267) radius 0.5 clockwise from (-6.5036, -29.6802) to (-6.65, -29.3267)
  arc A3 centre (-6.15, 4.3267) radius 0.5 clockwise from (-6.65, 4.3267) to (-6.5036, 4.6802)
  arc A4 centre (-2.3267, 8.15) radius 0.5 clockwise from (-2.6802, 8.5036) to (-2.3267, 8.65)
  arc A5 centre (31.3267, 8.15) radius 0.5 clockwise from (31.3267, 8.65) to (31.6802, 8.5036)
  arc A6 centre (35.15, 4.3267) radius 0.5 clockwise from (35.5036, 4.6802) to (35.65, 4.3267)
  arc A7 centre (35.15, -29.3267) radius 0.5 clockwise from (35.65, -29.3267) to (35.5036, -29.6802)
  arc A8 centre (31.3267, -33.15) radius 0.5 clockwise from (31.6802, -33.5036) to (31.3267, -33.65)
  circle C4 centre (59.2759, -95.0468) radius 15
  circle C5 centre (137.0235, -58.095) radius 7
  circle C6 centre (181.7869, -77.1992) radius 7
  circle C7 centre (230, -180) radius 7
  circle C8 centre (62.4153, -183.7959) radius 20
  circle C9 centre (68.5668, -277.091) radius 15
  circle C10 centre (156.0884, -281.9568) radius 7
  circle C11 centre (223.4596, -269.0631) radius 10
  circle C12 centre (224.2144, -445.9118) radius 10
  circle C13 centre (166.6949, -345.8239) radius 7
  circle C14 centre (135.1235, -425.1239) radius 15
  circle C15 centre (90, -440) radius 10
  circle C16 centre (120, -460) radius 7
  circle C17 centre (185.5991, -468.2067) radius 20
  circle C18 centre (105.4265, -496.3966) radius 7
  circle C19 centre (50.4667, -431.8087) radius 15
  circle C20 centre (60.2066, -358.0992) radius 20
  circle C21 centre (154.6891, -315.7507) radius 15
  circle C22 centre (210, -410) radius 7
  circle C23 centre (200, -300) radius 7
  circle C24 centre (173.431, -222.7107) radius 10
  circle C25 centre (80, -320) radius 10
  circle C26 centre (48.535, -233.4303) radius 10
  circle C27 centre (187.43, -169.7572) radius 20
  circle C28 centre (227.8855, -62.8164) radius 7
  circle C29 centre (138.5677, -94.5944) radius 15
  circle C30 centre (87.4071, -72.5429) radius 10
  circle C31 centre (60, -60) radius 7
  circle C32 centre (100, -120) radius 7
  circle C33 centre (182.0487, -124.3724) radius 7
  circle C34 centre (227.7787, -136.25) radius 10
  circle C35 centre (90.9515, -202.6198) radius 7
  circle C36 centre (45.7185, -314.2782) radius 10
  circle C37 centre (123.6741, -235.6181) radius 20
  circle C38 centre (181.6604, -262.778) radius 10
  circle C39 centre (220, -370) radius 10
  circle C40 centre (178.2661, -386.7903) radius 15
  circle C41 centre (140, -390) radius 7
  circle C42 centre (50.7881, -395.8727) radius 7
  circle C43 centre (67.1409, -471.833) radius 20
  circle C44 centre (227.7787, -494.7374) radius 10
  circle C45 centre (140, -490) radius 10
  circle C46 centre (51.7744, -504.4554) radius 10
  circle C47 centre (90, -400) radius 15
  circle C48 centre (125, -350) radius 20
  circle C49 centre (172.7099, -424.5516) radius 10
  circle C50 centre (207.9814, -331.3336) radius 20
  circle C51 centre (220.1507, -225.5922) radius 20
  circle C52 centre (116.4021, -275.0095) radius 10
  circle C53 centre (77.0561, -242.5691) radius 7
  circle C54 centre (130.6535, -184.5454) radius 10
  circle C55 centre (218.9336, -99.9179) radius 20
  circle C56 centre (140.8153, -144.1327) radius 15
  circle C57 centre (90, -150) radius 10
  circle C58 centre (45.0775, -139.6703) radius 10
  point P33 (20.4822, -461.493)
  point P37 (20.4822, -461.493)
  horizontal L13
  vertical L14
  horizontal L15
  vertical L16
  coincident P33 P37
extrude "Extrude7" add sketch "Sketch8" to an object
sketch "Sketch10" plane through (0, 0, 0) normal (-1, 0, 0) x axis (0, 0, 1)
  line L1 (13, -585) -> (-287, -585)
  line L2 (13, 15) -> (13, -585)
  line L3 (-287, 15) -> (13, 15)
  line L4 (-287, -585) -> (-287, 15)
  line L5 (-30, -50) -> (-245, -50)
  line L6 (-30, -105) -> (-30, -50)
  line L7 (-245, -105) -> (-30, -105)
  line L8 (-245, -50) -> (-245, -105)
  circle C1 centre (-259.5, -557.5) radius 2.5
  circle C2 centre (-14.5, -557.5) radius 2.5
  circle C3 centre (-259.5, -12.5) radius 2.5
  circle C4 centre (-14.5, -12.5) radius 2.5
  circle C5 centre (-230, -70) radius 6.75
  circle C6 centre (-200, -65) radius 6.75
  circle C7 centre (-161.6956, -62.1445) radius 6.75
  circle C8 centre (-130, -60) radius 6.75
  circle C9 centre (-88.9999, -63.301) radius 6.75
  circle C10 centre (-53.9141, -65.8527) radius 6.75
  circle C11 centre (-185.6453, -91.3697) radius 17.0965
  circle C12 centre (-143.5424, -81.8008) radius 8.9317
  circle C13 centre (-109.4135, -81.8008) radius 11.3847
  circle C14 centre (-66.9916, -91.3697) radius 13.5324
  circle C15 centre (-229.981, -95.1972) radius 4.0346
  arc A1 centre (-56.4567, -67.9193) radius 15.308 clockwise from (-65.2927, -55.4188) to (-59.8886, -53.0009)
  arc A2 centre (-60, -60) radius 7 clockwise from (-65.2927, -55.4188) to (-59.8886, -53.0009)
  arc A3 centre (-137.0235, -58.095) radius 7 clockwise from (-133.0091, -52.3605) to (-143.4776, -55.3848)
  arc A4 centre (-139.0445, -51.0994) radius 6.1658 clockwise from (-133.0091, -52.3605) to (-143.4776, -55.3848)
  arc A5 centre (-181.7869, -77.1992) radius 7 clockwise from (-182.5547, -84.1569) to (-181.2794, -70.2176)
  arc A6 centre (-169.4716, -57.7139) radius 17.1979 clockwise from (-175.6985, -73.7449) to (-181.2794, -70.2176)
  arc A7 centre (-181.7869, -77.1992) radius 7 clockwise from (-175.6985, -73.7449) to (-175.0541, -79.1148)
  arc A8 centre (-176.4641, -85.1172) radius 6.1658 clockwise from (-182.5547, -84.1569) to (-175.0541, -79.1148)
  circle C16 centre (-230, -180) radius 7
  circle C17 centre (-62.4153, -183.7959) radius 20
  circle C18 centre (-68.5668, -277.091) radius 15
  circle C19 centre (-156.0884, -281.9568) radius 7
  circle C20 centre (-223.4596, -269.0631) radius 10
  circle C21 centre (-224.2144, -445.9118) radius 10
  circle C22 centre (-166.6949, -345.8239) radius 7
  circle C23 centre (-135.1235, -425.1239) radius 15
  circle C24 centre (-90, -440) radius 10
  circle C25 centre (-120, -460) radius 7
  circle C26 centre (-185.5991, -468.2067) radius 20
  circle C27 centre (-105.4265, -496.3966) radius 7
  circle C28 centre (-50.4667, -431.8087) radius 15
  circle C29 centre (-60.2066, -358.0992) radius 20
  circle C30 centre (-154.6891, -315.7507) radius 15
  circle C31 centre (-210, -410) radius 7
  circle C32 centre (-200, -300) radius 7
  circle C33 centre (-173.431, -222.7107) radius 10
  circle C34 centre (-80, -320) radius 10
  circle C35 centre (-48.535, -233.4303) radius 10
  circle C36 centre (-187.43, -169.7572) radius 20
  arc A9 centre (-138.5677, -94.5944) radius 15 clockwise from (-127.5251, -104.7463) to (-143.0077, -80.2666)
  arc A10 centre (-126.5713, -87.0071) radius 17.7649 clockwise from (-127.5251, -104.7463) to (-143.0077, -80.2666)
  arc A11 centre (-87.4071, -72.5429) radius 10 clockwise from (-84.7984, -82.1966) to (-77.4095, -72.3278)
  arc A12 centre (-81.2141, -77.1797) radius 6.1658 clockwise from (-84.7984, -82.1966) to (-77.4095, -72.3278)
  circle C37 centre (-100, -120) radius 7
  circle C38 centre (-182.0487, -124.3724) radius 7
  circle C39 centre (-227.7787, -136.25) radius 10
  circle C40 centre (-90.9515, -202.6198) radius 7
  circle C41 centre (-45.7185, -314.2782) radius 10
  circle C42 centre (-123.6741, -235.6181) radius 20
  circle C43 centre (-181.6604, -262.778) radius 10
  circle C44 centre (-220, -370) radius 10
  circle C45 centre (-178.2661, -386.7903) radius 15
  circle C46 centre (-140, -390) radius 7
  circle C47 centre (-50.7881, -395.8727) radius 7
  circle C48 centre (-67.1409, -471.833) radius 20
  circle C49 centre (-227.7787, -494.7374) radius 10
  circle C50 centre (-140, -490) radius 10
  circle C51 centre (-51.7744, -504.4554) radius 10
  circle C52 centre (-90, -400) radius 15
  circle C53 centre (-125, -350) radius 20
  circle C54 centre (-172.7099, -424.5516) radius 10
  circle C55 centre (-207.9814, -331.3336) radius 20
  circle C56 centre (-220.1507, -225.5922) radius 20
  circle C57 centre (-116.4021, -275.0095) radius 10
  circle C58 centre (-77.0561, -242.5691) radius 7
  circle C59 centre (-130.6535, -184.5454) radius 10
  circle C60 centre (-140.8153, -144.1327) radius 15
  circle C61 centre (-90, -150) radius 10
  circle C62 centre (-45.0775, -139.6703) radius 10
  arc A13 centre (-227.8855, -62.8164) radius 7 clockwise from (-231.5982, -68.7507) to (-220.9494, -63.7597)
  arc A14 centre (-218.2305, -83.4163) radius 19.8438 clockwise from (-231.5982, -68.7507) to (-220.9494, -63.7597)
  arc A15 centre (-218.9336, -99.9179) radius 20 clockwise from (-200.4617, -92.2505) to (-236.6864, -90.7071)
  arc A16 centre (-218.2305, -83.4163) radius 19.8437 clockwise from (-200.4617, -92.2505) to (-236.6864, -90.7071)
  arc A17 centre (-59.2759, -95.0468) radius 15 clockwise from (-51.3106, -82.3364) to (-64.4574, -80.9701)
  arc A18 centre (-56.4567, -67.9193) radius 15.308 clockwise from (-51.3106, -82.3364) to (-64.4574, -80.9701)
  horizontal L5
  vertical L6
  horizontal L7
  vertical L8
  dimension "d55" diameter C5 = 13.5
  dimension "d56" diameter C6 = 13.5
  dimension "d57" diameter C7 = 13.5
  dimension "d58" diameter C8 = 13.5
  dimension "d59" diameter C9 = 13.5
  dimension "d60" diameter C10 = 13.5
extrude "Extrude8" cut sketch "Sketch10" profile of L7 C5 C6 C7 C8 C9 C10 C11 C12 C13 C14 C15 to an object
